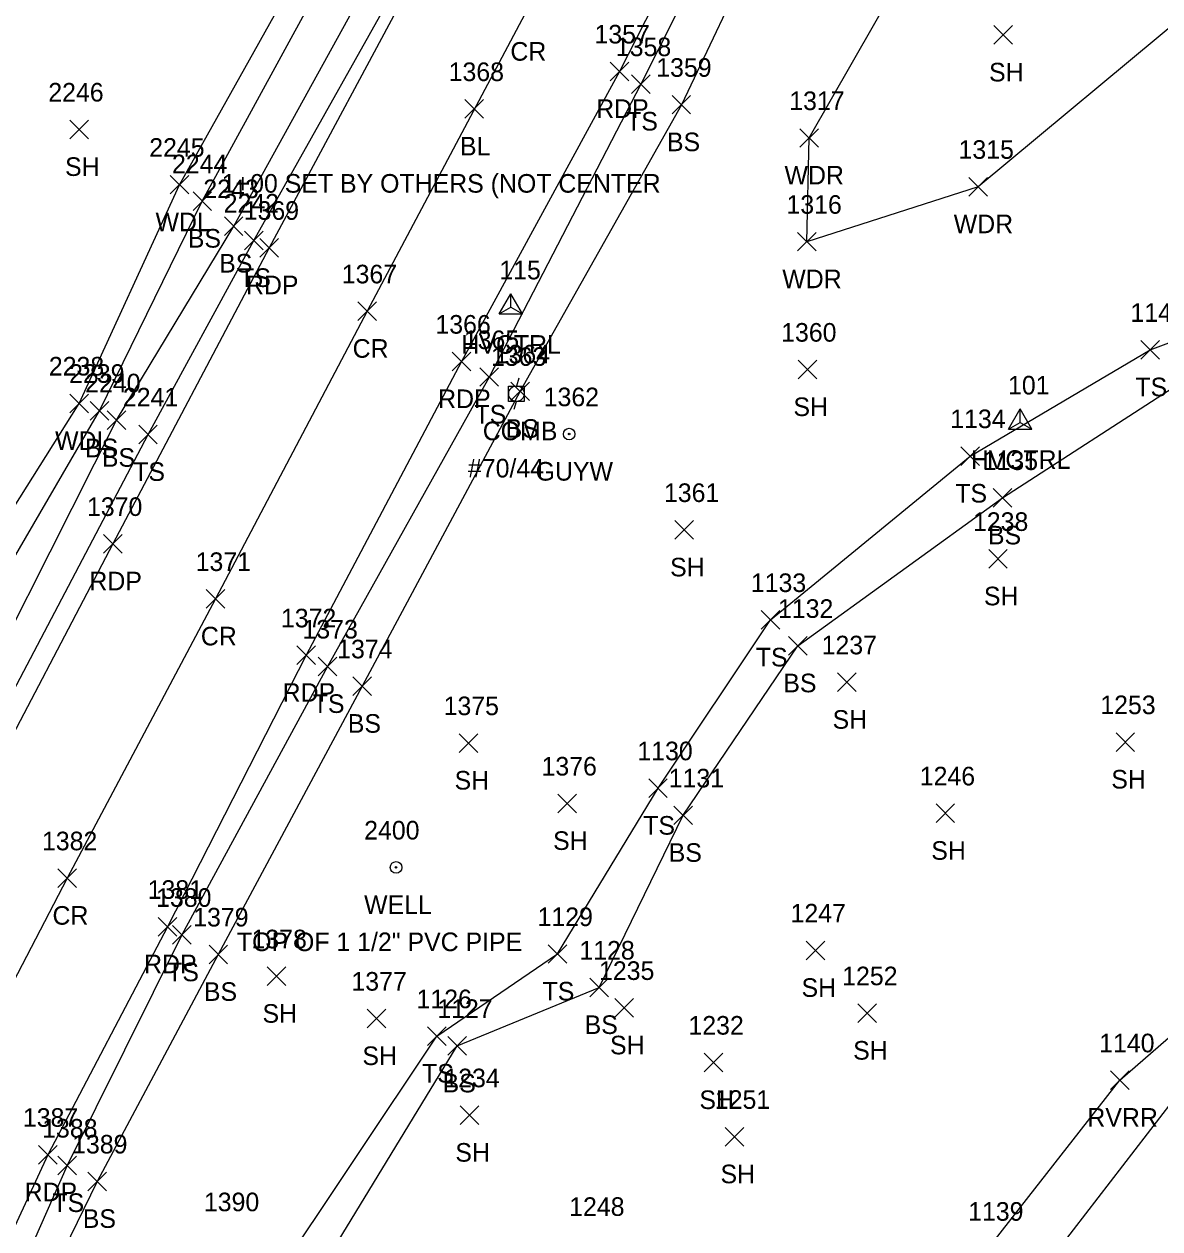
# Model space of a CAD drawing. Extents: x 1885914 to 1887218, y 756253 to 760620.
# Drawn here: x 1886578.6 to 1886700.7, y 760065.4 to 760195 of the extents above; entities that cross this region are included whole.
import ezdxf

# ---------------------------------------------------------------- set-up
doc = ezdxf.new("R2010")
doc.units = 0
for name, color, linetype in [('C_A', 7, 'Continuous'), ('C_C', 7, 'Continuous'), ('C_I', 7, 'Continuous'), ('C_TIC', 7, 'Continuous'), ('CPSM', 7, 'Continuous'), ('L_A', 7, 'Continuous'), ('L_I', 7, 'Continuous'), ('L_TIC', 7, 'Continuous'), ('LAWA', 7, 'Continuous'), ('LAWE', 7, 'Continuous'), ('LELB', 7, 'Continuous'), ('P_A', 7, 'Continuous'), ('P_I', 7, 'Continuous'), ('P_TIC', 7, 'Continuous'), ('PET', 7, 'Continuous'), ('PRC', 7, 'Continuous'), ('U_A', 7, 'Continuous'), ('U_C', 7, 'Continuous'), ('U_I', 7, 'Continuous'), ('UP', 7, 'Continuous'), ('UPGW', 7, 'Continuous'), ('UWW', 7, 'Continuous')]:
    doc.layers.add(name, color=color, linetype=linetype)

msp = doc.modelspace()

# ---------------------------------------------------------------- linework, layer by layer
at = {"layer": 'C_TIC'}
for points in [[(1886625.98, 760184.84), (1886627.98, 760186.84)], [(1886627.98, 760184.84), (1886625.98, 760186.84)]]:
    msp.add_lwpolyline(points, dxfattribs=at)
at = {"layer": 'CPSM'}
for p, q in [((1886629.67, 760163.8), (1886630.92, 760165.96)), ((1886632.17, 760163.8), (1886630.92, 760165.96)), ((1886630.92, 760164.52), (1886630.92, 760165.96)), ((1886629.67, 760163.8), (1886630.92, 760164.52)), ((1886630.92, 760164.52), (1886630.92, 760164.52)), ((1886630.92, 760164.52), (1886632.17, 760163.8)), ((1886629.67, 760163.8), (1886632.17, 760163.8)), ((1886684.44, 760151.41), (1886685.69, 760153.58)), ((1886684.44, 760151.41), (1886685.69, 760153.58)), ((1886684.44, 760151.41), (1886685.69, 760153.58)), ((1886684.44, 760151.41), (1886685.69, 760153.58)), ((1886684.44, 760151.41), (1886685.69, 760153.58)), ((1886684.44, 760151.41), (1886685.69, 760153.58)), ((1886686.94, 760151.41), (1886685.69, 760153.58)), ((1886685.69, 760152.14), (1886685.69, 760153.58)), ((1886686.94, 760151.41), (1886685.69, 760153.58)), ((1886685.69, 760152.14), (1886685.69, 760153.58)), ((1886686.94, 760151.41), (1886685.69, 760153.58)), ((1886685.69, 760152.14), (1886685.69, 760153.58)), ((1886686.94, 760151.41), (1886685.69, 760153.58)), ((1886685.69, 760152.14), (1886685.69, 760153.58)), ((1886686.94, 760151.41), (1886685.69, 760153.58)), ((1886685.69, 760152.14), (1886685.69, 760153.58)), ((1886686.94, 760151.41), (1886685.69, 760153.58)), ((1886685.69, 760152.14), (1886685.69, 760153.58)), ((1886684.44, 760151.41), (1886685.69, 760152.14)), ((1886684.44, 760151.41), (1886685.69, 760152.14)), ((1886684.44, 760151.41), (1886685.69, 760152.14)), ((1886684.44, 760151.41), (1886685.69, 760152.14)), ((1886684.44, 760151.41), (1886685.69, 760152.14)), ((1886684.44, 760151.41), (1886685.69, 760152.14)), ((1886685.69, 760152.14), (1886685.69, 760152.14)), ((1886685.69, 760152.14), (1886686.94, 760151.41)), ((1886685.69, 760152.14), (1886685.69, 760152.14)), ((1886685.69, 760152.14), (1886686.94, 760151.41)), ((1886685.69, 760152.14), (1886685.69, 760152.14)), ((1886685.69, 760152.14), (1886686.94, 760151.41)), ((1886685.69, 760152.14), (1886685.69, 760152.14)), ((1886685.69, 760152.14), (1886686.94, 760151.41)), ((1886685.69, 760152.14), (1886685.69, 760152.14)), ((1886685.69, 760152.14), (1886686.94, 760151.41)), ((1886685.69, 760152.14), (1886685.69, 760152.14)), ((1886685.69, 760152.14), (1886686.94, 760151.41)), ((1886684.44, 760151.41), (1886686.94, 760151.41)), ((1886684.44, 760151.41), (1886686.94, 760151.41)), ((1886684.44, 760151.41), (1886686.94, 760151.41)), ((1886684.44, 760151.41), (1886686.94, 760151.41)), ((1886684.44, 760151.41), (1886686.94, 760151.41)), ((1886684.44, 760151.41), (1886686.94, 760151.41))]:
    msp.add_line(p, q, dxfattribs=at)
at = {"layer": 'L_TIC'}
for points in [[(1886682.85, 760192.8), (1886684.85, 760194.8)], [(1886684.85, 760192.8), (1886682.85, 760194.8)], [(1886643.91, 760187.52), (1886645.91, 760189.52)], [(1886645.91, 760187.52), (1886643.91, 760189.52)], [(1886648.26, 760185.3), (1886650.26, 760187.3)], [(1886650.26, 760185.3), (1886648.26, 760187.3)], [(1886583.51, 760182.64), (1886585.51, 760184.64)], [(1886585.51, 760182.64), (1886583.51, 760184.64)], [(1886661.99, 760181.72), (1886663.99, 760183.72)], [(1886663.99, 760181.72), (1886661.99, 760183.72)], [(1886594.31, 760176.7), (1886596.31, 760178.7)], [(1886596.31, 760176.7), (1886594.31, 760178.7)], [(1886680.18, 760176.48), (1886682.18, 760178.48)], [(1886682.18, 760176.48), (1886680.18, 760178.48)], [(1886596.76, 760174.93), (1886598.76, 760176.93)], [(1886598.76, 760174.93), (1886596.76, 760176.93)], [(1886600.13, 760172.25), (1886602.13, 760174.25)], [(1886602.13, 760172.25), (1886600.13, 760174.25)], [(1886602.31, 760170.7), (1886604.31, 760172.7)], [(1886604.31, 760170.7), (1886602.31, 760172.7)], [(1886661.74, 760170.57), (1886663.74, 760172.57)], [(1886663.74, 760170.57), (1886661.74, 760172.57)], [(1886698.66, 760158.95), (1886700.66, 760160.95)], [(1886700.66, 760158.95), (1886698.66, 760160.95)], [(1886661.82, 760156.82), (1886663.82, 760158.82)], [(1886663.82, 760156.82), (1886661.82, 760158.82)], [(1886627.61, 760156.02), (1886629.61, 760158.02)], [(1886629.61, 760156.02), (1886627.61, 760158.02)], [(1886630.93, 760154.48), (1886632.93, 760156.48)], [(1886632.93, 760154.48), (1886630.93, 760156.48)], [(1886583.52, 760153.18), (1886585.52, 760155.18)], [(1886585.52, 760153.18), (1886583.52, 760155.18)], [(1886585.71, 760152.39), (1886587.71, 760154.39)], [(1886587.71, 760152.39), (1886585.71, 760154.39)], [(1886587.52, 760151.37), (1886589.52, 760153.37)], [(1886589.52, 760151.37), (1886587.52, 760153.37)], [(1886590.92, 760149.85), (1886592.92, 760151.85)], [(1886592.92, 760149.85), (1886590.92, 760151.85)], [(1886679.3, 760147.52), (1886681.3, 760149.52)], [(1886681.3, 760147.52), (1886679.3, 760149.52)], [(1886682.78, 760143.02), (1886684.78, 760145.02)], [(1886684.78, 760143.02), (1886682.78, 760145.02)], [(1886648.56, 760139.58), (1886650.56, 760141.58)], [(1886650.56, 760139.58), (1886648.56, 760141.58)], [(1886682.3, 760136.47), (1886684.3, 760138.47)], [(1886684.3, 760136.47), (1886682.3, 760138.47)], [(1886657.85, 760129.9), (1886659.85, 760131.9)], [(1886659.85, 760129.9), (1886657.85, 760131.9)], [(1886660.77, 760127.12), (1886662.77, 760129.12)], [(1886662.77, 760127.12), (1886660.77, 760129.12)], [(1886610.22, 760124.9), (1886612.22, 760126.9)], [(1886612.22, 760124.9), (1886610.22, 760126.9)], [(1886613.95, 760122.77), (1886615.95, 760124.77)], [(1886615.95, 760122.77), (1886613.95, 760124.77)], [(1886666.04, 760123.2), (1886668.04, 760125.2)], [(1886668.04, 760123.2), (1886666.04, 760125.2)], [(1886625.39, 760116.66), (1886627.39, 760118.66)], [(1886627.39, 760116.66), (1886625.39, 760118.66)], [(1886695.99, 760116.77), (1886697.99, 760118.77)], [(1886697.99, 760116.77), (1886695.99, 760118.77)], [(1886645.75, 760111.81), (1886647.75, 760113.81)], [(1886647.75, 760111.81), (1886645.75, 760113.81)], [(1886635.98, 760110.17), (1886637.98, 760112.17)], [(1886637.98, 760110.17), (1886635.98, 760112.17)], [(1886648.45, 760108.89), (1886650.45, 760110.89)], [(1886650.45, 760108.89), (1886648.45, 760110.89)], [(1886676.64, 760109.11), (1886678.64, 760111.11)], [(1886678.64, 760109.11), (1886676.64, 760111.11)], [(1886594.57, 760096.05), (1886596.57, 760098.05)], [(1886596.57, 760096.05), (1886594.57, 760098.05)], [(1886598.48, 760093.94), (1886600.48, 760095.94)], [(1886600.48, 760093.94), (1886598.48, 760095.94)], [(1886634.93, 760093.98), (1886636.93, 760095.98)], [(1886636.93, 760093.98), (1886634.93, 760095.98)], [(1886662.69, 760094.37), (1886664.69, 760096.37)], [(1886664.69, 760094.37), (1886662.69, 760096.37)], [(1886604.74, 760091.59), (1886606.74, 760093.59)], [(1886606.74, 760091.59), (1886604.74, 760093.59)], [(1886639.42, 760090.38), (1886641.42, 760092.38)], [(1886641.42, 760090.38), (1886639.42, 760092.38)], [(1886642.1, 760088.19), (1886644.1, 760090.19)], [(1886644.1, 760088.19), (1886642.1, 760090.19)], [(1886668.24, 760087.62), (1886670.24, 760089.62)], [(1886670.24, 760087.62), (1886668.24, 760089.62)], [(1886615.49, 760087.04), (1886617.49, 760089.04)], [(1886617.49, 760087.04), (1886615.49, 760089.04)], [(1886621.97, 760085.15), (1886623.97, 760087.15)], [(1886623.97, 760085.15), (1886621.97, 760087.15)], [(1886624.15, 760084.1), (1886626.15, 760086.1)], [(1886626.15, 760084.1), (1886624.15, 760086.1)], [(1886651.72, 760082.31), (1886653.72, 760084.31)], [(1886653.72, 760082.31), (1886651.72, 760084.31)], [(1886695.4, 760080.41), (1886697.4, 760082.41)], [(1886697.4, 760080.41), (1886695.4, 760082.41)], [(1886625.47, 760076.65), (1886627.47, 760078.65)], [(1886627.47, 760076.65), (1886625.47, 760078.65)], [(1886653.98, 760074.33), (1886655.98, 760076.33)], [(1886655.98, 760074.33), (1886653.98, 760076.33)], [(1886582.24, 760071.24), (1886584.24, 760073.24)], [(1886584.24, 760071.24), (1886582.24, 760073.24)], [(1886585.46, 760069.53), (1886587.46, 760071.53)], [(1886587.46, 760069.53), (1886585.46, 760071.53)]]:
    msp.add_lwpolyline(points, dxfattribs=at)
at = {"layer": 'LAWA'}
for points in [[(1886557.49, 760303.87), (1886591.46, 760287.38), (1886586.6, 760261.32), (1886572.4, 760231.51), (1886560.84, 760204.17), (1886553.53, 760184.95), (1886554.61, 760165.79), (1886555.43, 760150.16), (1886559.73, 760135.93), (1886571.71, 760133.88), (1886584.52, 760154.18), (1886595.31, 760177.7), (1886612.55, 760208.5), (1886627.73, 760237.63), (1886641.55, 760264.82), (1886659.69, 760306.49), (1886641.28, 760308.88), (1886618.53, 760315.27), (1886578.46, 760329), (1886533.46, 760348.84), (1886508.34, 760359)], [(1886739.18, 760176.38), (1886732.49, 760188.8), (1886703.91, 760196.4), (1886681.18, 760177.48), (1886662.74, 760171.57), (1886662.99, 760182.72), (1886681.62, 760215.3), (1886695.77, 760245.06), (1886708.75, 760275.76), (1886734.57, 760330.32)]]:
    msp.add_lwpolyline(points, dxfattribs=at)
at = {"layer": 'LAWE'}
msp.add_lwpolyline([(1886643.57, 759950.66), (1886647.93, 759967.68), (1886650.25, 759980.54), (1886657.27, 760004.64), (1886666.09, 760031.44), (1886675.36, 760057.62), (1886682.23, 760063.3), (1886696.4, 760081.41), (1886713.46, 760096.25), (1886729.03, 760111.8), (1886751.04, 760124.89), (1886757.81, 760125.78), (1886762.25, 760134.23), (1886778.71, 760146.09), (1886791.91, 760151.37), (1886806.2, 760167.73), (1886818.04, 760166.72), (1886829.4, 760164.97), (1886849.11, 760176.99)], dxfattribs=at)
at = {"layer": 'LELB'}
for points in [[(1886566.15, 760118.03), (1886586.71, 760153.39), (1886597.76, 760175.93), (1886614.93, 760207.48), (1886633.43, 760234.81), (1886648.4, 760263.02), (1886665.33, 760301.86), (1886680.82, 760329.69), (1886690.65, 760354.87)], [(1886569.48, 760114.6), (1886588.52, 760152.37), (1886601.13, 760173.25), (1886619.2, 760206.04), (1886634.53, 760234.24), (1886649.4, 760262.46), (1886668.06, 760300.13), (1886683.15, 760328.96), (1886694.25, 760353.25)], [(1886571.83, 760112.64), (1886591.92, 760150.85), (1886603.31, 760171.7), (1886621.88, 760204.85), (1886636.21, 760233.06), (1886650.97, 760261.46), (1886669.74, 760299.13), (1886684.78, 760328.15), (1886696.37, 760352.36)], [(1886722.34, 760338.16), (1886708.2, 760311.94), (1886695.5, 760287.88), (1886679.14, 760254.71), (1886661.55, 760221.54), (1886644.91, 760188.52), (1886628.61, 760157.02), (1886611.22, 760125.9), (1886595.57, 760097.05), (1886583.24, 760072.24), (1886569.53, 760041.34), (1886558.98, 760023.45), (1886545.01, 759997.38), (1886527.64, 759964.02), (1886508.85, 759921.99)], [(1886725.27, 760338.09), (1886712.33, 760310.28), (1886698.46, 760286.41), (1886683.25, 760252.31), (1886665.56, 760220.6), (1886649.26, 760186.3), (1886631.93, 760155.48), (1886614.95, 760123.77), (1886599.48, 760094.94), (1886586.46, 760070.53), (1886572.04, 760041.07), (1886559.72, 760022.59), (1886545.87, 759996.97), (1886529.41, 759963.14), (1886510.6, 759921.25), (1886501.24, 759900.36), (1886492.69, 759872.91), (1886485.39, 759846.95), (1886480.56, 759824.59), (1886476.3, 759808.27), (1886477.13, 759795.21)], [(1887191.67, 760127.4), (1887162.59, 760142.97), (1887139.96, 760151.52), (1887098.78, 760169.34), (1887064.77, 760179.63), (1887039.44, 760184.45), (1887015.43, 760186.04), (1886988.17, 760195.78), (1886958.13, 760192.47), (1886941.93, 760196.3), (1886915.34, 760186.03), (1886875.72, 760169.95), (1886843.17, 760163.26), (1886814.02, 760157.37), (1886794.47, 760144.1), (1886725.54, 760103.53), (1886704.64, 760082.53), (1886687.39, 760060.16), (1886675.38, 760043.91), (1886662.89, 760014.32), (1886651.59, 759963.58), (1886647.85, 759929.2)], [(1886569.47, 759932.79), (1886578.55, 759960.06), (1886589.25, 759986.28), (1886598.57, 760012.52), (1886604.77, 760034.06), (1886609.07, 760058.69), (1886625.15, 760085.1), (1886640.42, 760091.38), (1886649.45, 760109.89), (1886661.77, 760128.12), (1886683.78, 760144.02), (1886702.73, 760156.3), (1886717, 760162.7), (1886740.68, 760172.2), (1886760.93, 760185.46), (1886776.22, 760178.86), (1886795.79, 760185.28), (1886813.44, 760184.92), (1886834.73, 760176.46), (1886849.11, 760176.99)], [(1886572.3, 759803.95), (1886568.6, 759823.21), (1886564.73, 759854.7), (1886563.87, 759883.9), (1886566.65, 759905.78), (1886566.1, 759932.48), (1886575.22, 759961.15), (1886584.71, 759987.76), (1886595.18, 760013.31), (1886601.19, 760034.22), (1886605.14, 760059.41), (1886622.97, 760086.15), (1886635.93, 760094.98), (1886646.75, 760112.81), (1886658.85, 760130.9), (1886680.3, 760148.52), (1886699.66, 760159.95), (1886715.31, 760165.82), (1886739.18, 760176.38)]]:
    msp.add_lwpolyline(points, dxfattribs=at)
at = {"layer": 'P_TIC'}
for points in [[(1886641.61, 760188.88), (1886643.61, 760190.88)], [(1886643.61, 760188.88), (1886641.61, 760190.88)], [(1886603.96, 760169.92), (1886605.96, 760171.92)], [(1886605.96, 760169.92), (1886603.96, 760171.92)], [(1886614.49, 760163.09), (1886616.49, 760165.09)], [(1886616.49, 760163.09), (1886614.49, 760165.09)], [(1886624.62, 760157.68), (1886626.62, 760159.68)], [(1886626.62, 760157.68), (1886624.62, 760159.68)], [(1886587.13, 760138.08), (1886589.13, 760140.08)], [(1886589.13, 760138.08), (1886587.13, 760140.08)], [(1886598.17, 760132.16), (1886600.17, 760134.16)], [(1886600.17, 760132.16), (1886598.17, 760134.16)], [(1886607.91, 760126.1), (1886609.91, 760128.1)], [(1886609.91, 760126.1), (1886607.91, 760128.1)], [(1886582.22, 760102.13), (1886584.22, 760104.13)], [(1886584.22, 760102.13), (1886582.22, 760104.13)], [(1886593.01, 760096.91), (1886595.01, 760098.91)], [(1886595.01, 760096.91), (1886593.01, 760098.91)], [(1886580.16, 760072.4), (1886582.16, 760074.4)], [(1886582.16, 760072.4), (1886580.16, 760074.4)]]:
    msp.add_lwpolyline(points, dxfattribs=at)
at = {"layer": 'PET'}
for points in [[(1886697.38, 760351.34), (1886683.55, 760324.32), (1886670.92, 760299), (1886655.54, 760267.57), (1886637.84, 760233.45), (1886621.76, 760202.26), (1886604.96, 760170.92), (1886588.13, 760139.08), (1886573.73, 760111.63), (1886569.92, 760108.66), (1886558.78, 760086.23), (1886539.06, 760048.09), (1886538, 760043.12), (1886529.58, 760026.84), (1886519.95, 760007.47), (1886505.21, 759975.04), (1886485.32, 759931.76)], [(1886719.61, 760339.51), (1886705.93, 760312.96), (1886693.41, 760288.8), (1886676.56, 760255.91), (1886659.38, 760222.81), (1886642.61, 760189.88), (1886625.62, 760158.68), (1886608.91, 760127.1), (1886594.01, 760097.91), (1886581.16, 760073.4), (1886568, 760045.02), (1886556.6, 760025.44), (1886542.61, 759998.54), (1886526.14, 759964.92), (1886507.07, 759922.75)]]:
    msp.add_lwpolyline(points, dxfattribs=at)
at = {"layer": 'PRC'}
msp.add_lwpolyline([(1886708.51, 760345.16), (1886695.27, 760318.5), (1886682.3, 760293.2), (1886665.98, 760261.32), (1886649.02, 760227.78), (1886632.44, 760196.03), (1886615.49, 760164.09), (1886599.17, 760133.16), (1886583.22, 760103.13), (1886570.57, 760078.83), (1886555.85, 760051.11), (1886540.62, 760021), (1886531.87, 760002.72), (1886516.05, 759969.43), (1886496.99, 759926.69)], dxfattribs=at)
at = {"layer": 'UP'}
for p, q in [((1886631.78, 760156.88), (1886631.53, 760156.05)), ((1886630.69, 760154.38), (1886630.69, 760156.05)), ((1886630.69, 760156.05), (1886632.36, 760156.05)), ((1886632.36, 760156.05), (1886632.36, 760154.38)), ((1886632.36, 760154.38), (1886630.69, 760154.38)), ((1886631.28, 760153.55), (1886631.53, 760154.38)), ((1886631.53, 760155.22), (1886631.53, 760155.22))]:
    msp.add_line(p, q, dxfattribs=at)
msp.add_circle((1886631.53, 760155.22), 0.833, dxfattribs=at)
at = {"layer": 'UPGW'}
for radius in [0.625, 0.0833]:
    msp.add_circle((1886637.2, 760150.88), radius, dxfattribs=at)
at = {"layer": 'UWW'}
for radius in [0.625, 0.0833]:
    msp.add_circle((1886618.59, 760104.29), radius, dxfattribs=at)

# ---------------------------------------------------------------- texts
at = {"layer": 'C_A'}
for s, p in [('BL', (1886625.46, 760180.84)), ('HVCTRL', (1886625.61, 760159.52)), ('HVCTRL', (1886680.38, 760147.14)), ('HVCTRL', (1886680.38, 760147.14)), ('HVCTRL', (1886680.38, 760147.14)), ('HVCTRL', (1886680.38, 760147.14)), ('HVCTRL', (1886680.38, 760147.14)), ('HVCTRL', (1886680.38, 760147.14))]:
    msp.add_text(s, height=2, dxfattribs=at).set_placement(p)
at = {"layer": 'C_C'}
msp.add_text('1+00 SET BY OTHERS (NOT CENTER', height=2, dxfattribs=at).set_placement((1886599.85, 760176.84))
at = {"layer": 'C_I'}
for s, p in [('1368', (1886624.24, 760188.84)), ('115', (1886629.69, 760167.52)), ('101', (1886684.38, 760155.14)), ('101', (1886684.38, 760155.14)), ('101', (1886684.38, 760155.14)), ('101', (1886684.38, 760155.14)), ('101', (1886684.38, 760155.14)), ('101', (1886684.38, 760155.14))]:
    msp.add_text(s, height=2, dxfattribs=at).set_placement(p)
at = {"layer": 'L_A'}
for s, p in [('SH', (1886682.34, 760188.8)), ('TS', (1886643.32, 760183.52)), ('BS', (1886647.71, 760181.3)), ('SH', (1886583, 760178.64)), ('WDR', (1886660.35, 760177.72)), ('WDL', (1886592.73, 760172.7)), ('WDR', (1886678.54, 760172.48)), ('BS', (1886596.2, 760170.93)), ('BS', (1886599.57, 760168.25)), ('TS', (1886601.72, 760166.7)), ('WDR', (1886660.11, 760166.57)), ('TS', (1886698.07, 760154.95)), ('SH', (1886661.31, 760152.82)), ('TS', (1886627.02, 760152.02)), ('BS', (1886630.37, 760150.48)), ('WDL', (1886581.93, 760149.18)), ('BS', (1886585.15, 760148.39)), ('BS', (1886586.96, 760147.37)), ('TS', (1886590.33, 760145.85)), ('TS', (1886678.71, 760143.52)), ('BS', (1886682.22, 760139.02)), ('SH', (1886648.05, 760135.58)), ('SH', (1886681.79, 760132.47)), ('TS', (1886657.26, 760125.9)), ('BS', (1886660.22, 760123.12)), ('TS', (1886609.63, 760120.9)), ('BS', (1886613.4, 760118.77)), ('SH', (1886665.52, 760119.2)), ('SH', (1886624.88, 760112.66)), ('SH', (1886695.48, 760112.77)), ('TS', (1886645.16, 760107.81)), ('SH', (1886635.47, 760106.17)), ('BS', (1886647.9, 760104.89)), ('SH', (1886676.13, 760105.11)), ('TS', (1886593.98, 760092.05)), ('BS', (1886597.93, 760089.94)), ('TS', (1886634.34, 760089.98)), ('SH', (1886662.18, 760090.37)), ('SH', (1886604.23, 760087.59)), ('BS', (1886638.86, 760086.38)), ('SH', (1886641.59, 760084.19)), ('SH', (1886667.73, 760083.62)), ('SH', (1886614.97, 760083.04)), ('TS', (1886621.38, 760081.15)), ('BS', (1886623.59, 760080.1)), ('SH', (1886651.2, 760078.31)), ('RVRR', (1886692.91, 760076.41)), ('SH', (1886624.96, 760072.65)), ('SH', (1886653.47, 760070.33)), ('TS', (1886581.64, 760067.24)), ('BS', (1886584.91, 760065.53))]:
    msp.add_text(s, height=2, dxfattribs=at).set_placement(p)
at = {"layer": 'L_I'}
for s, p in [('1358', (1886642.22, 760191.52)), ('1359', (1886646.56, 760189.3)), ('2246', (1886581.2, 760186.64)), ('1317', (1886660.86, 760185.72)), ('2245', (1886592.05, 760180.7)), ('1315', (1886679.06, 760180.48)), ('2244', (1886594.5, 760178.93)), ('2243', (1886597.87, 760176.25)), ('2242', (1886600.06, 760174.7)), ('1316', (1886660.56, 760174.57)), ('1145', (1886697.54, 760162.95)), ('1365', (1886625.87, 760160.02)), ('1360', (1886659.99, 760160.82)), ('1364', (1886629.19, 760158.48)), ('2238', (1886581.26, 760157.18)), ('2239', (1886583.44, 760156.39)), ('2240', (1886585.17, 760155.37)), ('2241', (1886589.22, 760153.85)), ('1134', (1886678.17, 760151.52)), ('1135', (1886681.66, 760147.02)), ('1361', (1886647.39, 760143.58)), ('1238', (1886680.61, 760140.47)), ('1133', (1886656.73, 760133.9)), ('1132', (1886659.65, 760131.12)), ('1373', (1886608.53, 760128.9)), ('1374', (1886612.26, 760126.77)), ('1237', (1886664.34, 760127.2)), ('1375', (1886623.7, 760120.66)), ('1253', (1886694.3, 760120.77)), ('1130', (1886644.53, 760115.81)), ('1376', (1886634.23, 760114.17)), ('1131', (1886647.9, 760112.89)), ('1246', (1886674.89, 760113.11)), ('1380', (1886592.79, 760100.05)), ('1379', (1886596.78, 760097.94)), ('1129', (1886633.8, 760097.98)), ('1247', (1886661, 760098.37)), ('1378', (1886603.05, 760095.59)), ('1128', (1886638.3, 760094.38)), ('1235', (1886640.41, 760092.19)), ('1252', (1886666.55, 760091.62)), ('1377', (1886613.79, 760091.04)), ('1126', (1886620.79, 760089.15)), ('1127', (1886623.02, 760088.1)), ('1232', (1886650.02, 760086.31)), ('1140', (1886694.18, 760084.41)), ('1234', (1886623.78, 760080.65)), ('1251', (1886652.86, 760078.33)), ('1388', (1886580.54, 760075.24)), ('1389', (1886583.76, 760073.53)), ('1390', (1886597.93, 760067.32)), ('1248', (1886637.2, 760066.82)), ('1139', (1886680.09, 760066.3))]:
    msp.add_text(s, height=2, dxfattribs=at).set_placement(p)
at = {"layer": 'P_A'}
for s, p in [('CR', (1886630.88, 760191.03)), ('RDP', (1886640.1, 760184.88)), ('RDP', (1886602.45, 760165.92)), ('CR', (1886613.92, 760159.09)), ('RDP', (1886623.11, 760153.68)), ('RDP', (1886585.62, 760134.08)), ('CR', (1886597.6, 760128.16)), ('RDP', (1886606.39, 760122.1)), ('CR', (1886581.65, 760098.13)), ('RDP', (1886591.5, 760092.91)), ('RDP', (1886578.65, 760068.4))]:
    msp.add_text(s, height=2, dxfattribs=at).set_placement(p)
at = {"layer": 'P_I'}
for s, p in [('1357', (1886639.92, 760192.88)), ('1369', (1886602.21, 760173.92)), ('1367', (1886612.75, 760167.09)), ('1366', (1886622.82, 760161.68)), ('1370', (1886585.36, 760142.08)), ('1371', (1886597.04, 760136.16)), ('1372', (1886606.21, 760130.1)), ('1382', (1886580.52, 760106.13)), ('1381', (1886591.88, 760100.91)), ('1387', (1886578.47, 760076.4))]:
    msp.add_text(s, height=2, dxfattribs=at).set_placement(p)
at = {"layer": 'U_A'}
for s, p in [('COMB', (1886627.91, 760150.22)), ('GUYW', (1886633.59, 760145.88)), ('WELL', (1886615.15, 760099.29))]:
    msp.add_text(s, height=2, dxfattribs=at).set_placement(p)
at = {"layer": 'U_C'}
for s, p in [('#70/44', (1886626.32, 760146.22)), ('TOP OF 1 1/2" PVC PIPE', (1886601.48, 760095.29))]:
    msp.add_text(s, height=2, dxfattribs=at).set_placement(p)
at = {"layer": 'U_I'}
for s, p in [('1363', (1886628.79, 760158.22)), ('1362', (1886634.46, 760153.88)), ('2400', (1886615.16, 760107.29))]:
    msp.add_text(s, height=2, dxfattribs=at).set_placement(p)

doc.saveas('drawing.dxf')
